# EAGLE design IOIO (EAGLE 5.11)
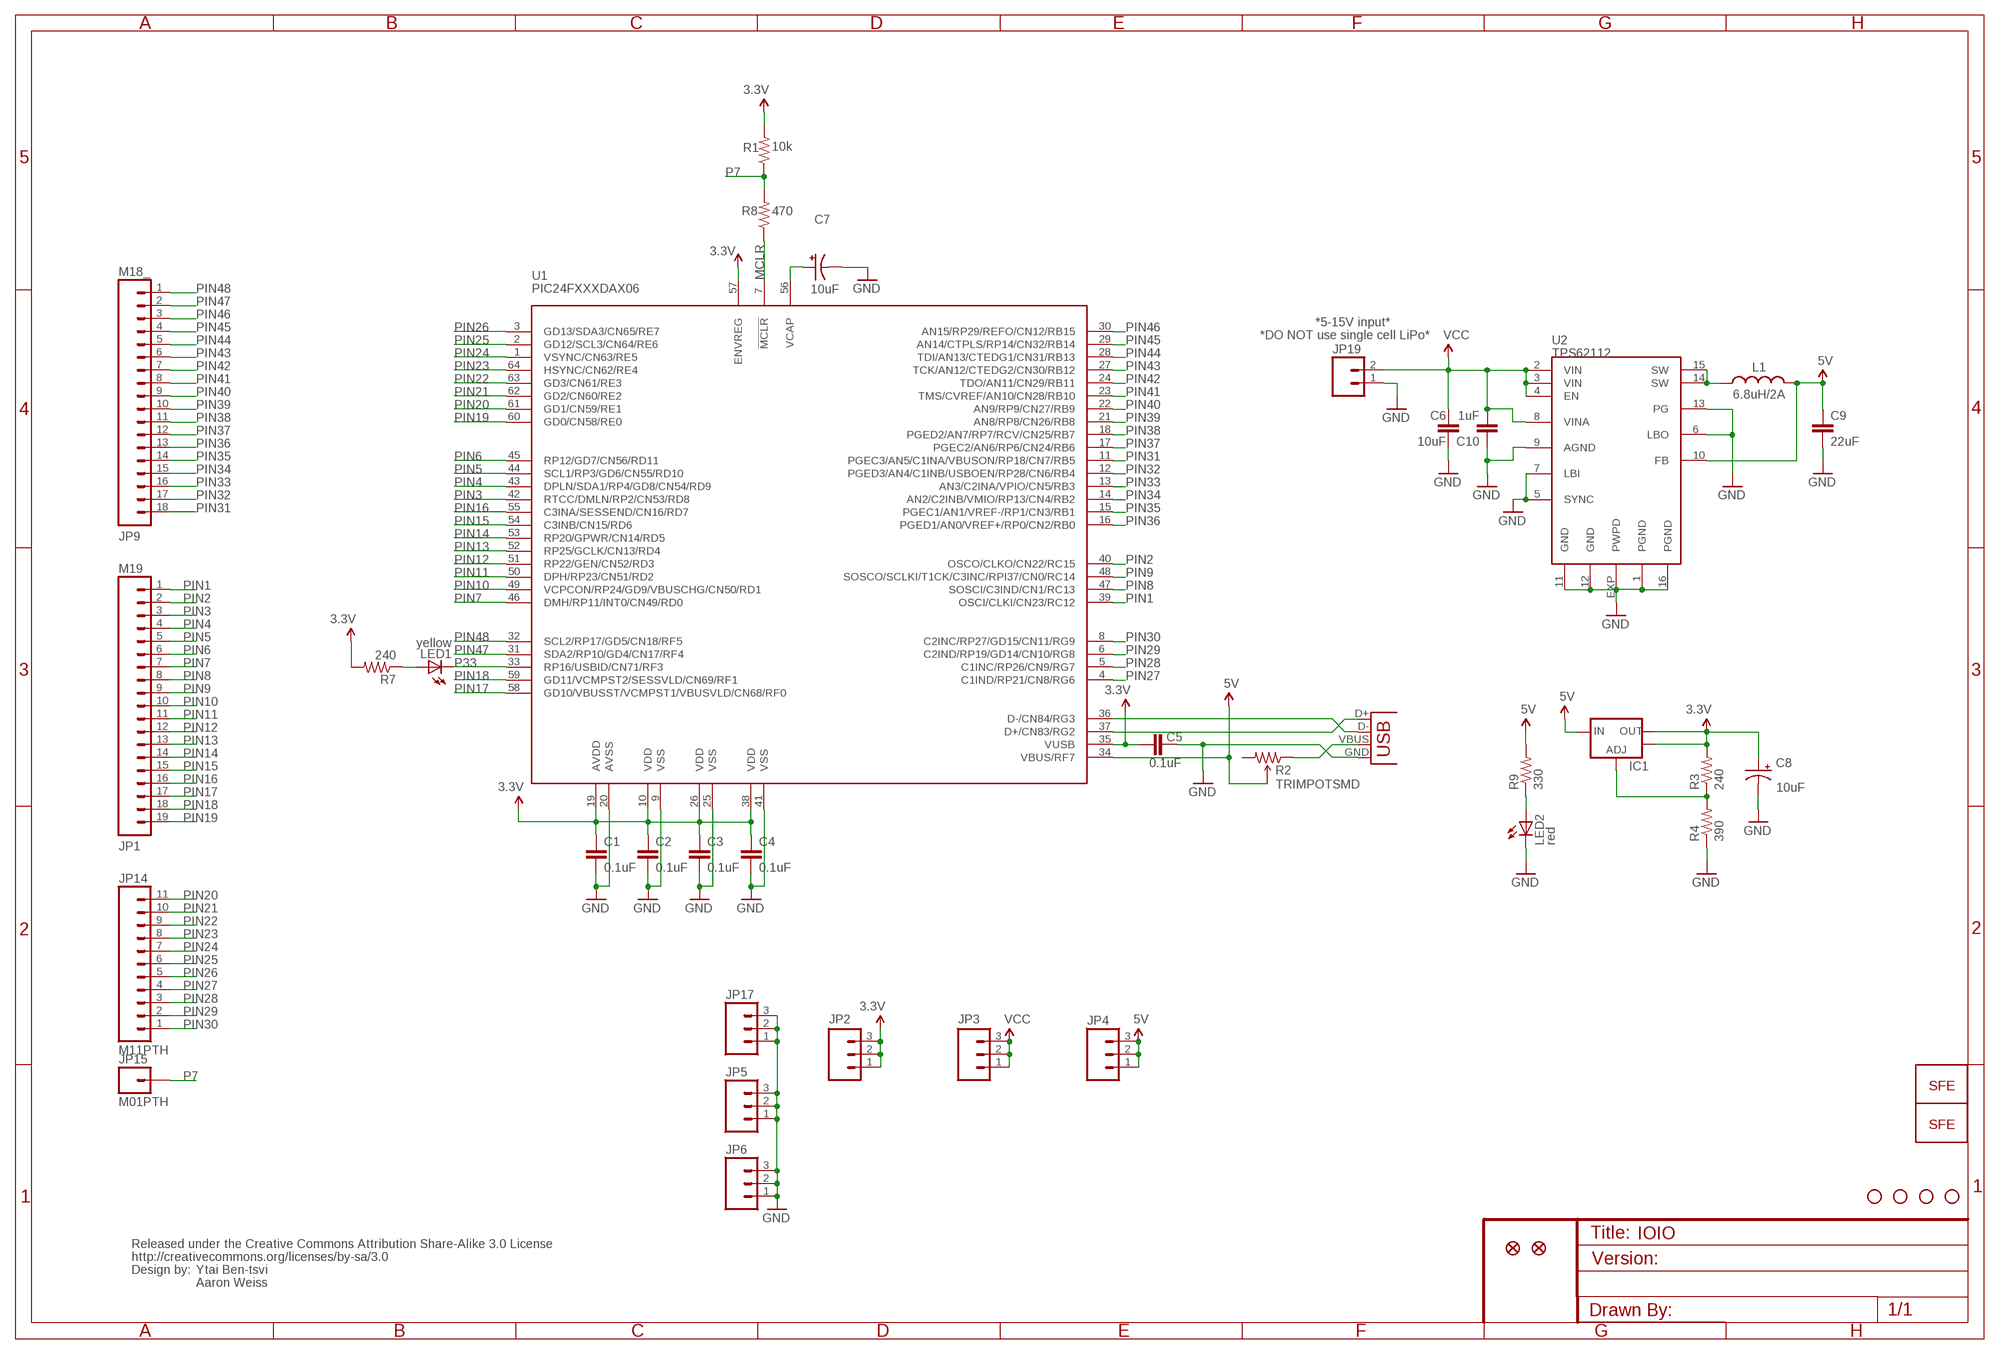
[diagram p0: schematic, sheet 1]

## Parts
C1  0.1uF  CAP0402-CAP  [0402-CAP]
C2  0.1uF  CAP0402-CAP  [0402-CAP]
C3  0.1uF  CAP0402-CAP  [0402-CAP]
C4  0.1uF  CAP0402-CAP  [0402-CAP]
C5  0.1uF  CAP0402-CAP  [0402-CAP]
C6  10uF  CAP1210  [1210]
C7  10uF  CAP_POL1206  [EIA3216]
C8  10uF  CAP_POL1206  [EIA3216]
C9  22uF  CAP1210  [1210]
C10  1uF  CAP0805  [0805]
IC1  V_REG_LM1117SOT223  [SOT223]
JP1  M19  [1X19]
JP2  M03PTH  [1X03]
JP3  M03PTH  [1X03]
JP4  M03PTH  [1X03]
JP5  M03PTH  [1X03]
JP6  M03PTH  [1X03]
JP7  FIDUCIAL1X2  [FIDUCIAL-1X2]
JP8  LOGO-SFENEW  [SFE-NEW-WEBLOGO]
JP9  M18_  [1X18]
JP10  STAND-OFF  [STAND-OFF]
JP11  STAND-OFF  [STAND-OFF]
JP12  STAND-OFF  [STAND-OFF]
JP13  STAND-OFF  [STAND-OFF]
JP14  M11PTH  [1X11]
JP15  M01PTH  [1X01]
JP16  LOGO-SFESK  [SFE-LOGO-FLAME]
JP17  M03PTH  [1X03]
JP18  FIDUCIAL1X2  [FIDUCIAL-1X2]
JP19  M02-JST-2MM-SMT  [JST-2-SMD]
L1  6.8uH/2A  INDUCTORSRU5028  [SRU5028]
LED1  yellow  LED0603  [LED-0603]
LED2  red  LED0603  [LED-0603]
R1  10k  RESISTOR0402-RES  [0402-RES]
R2  TRIMPOTSMD  [TRIMPOT-3MM]
R3  240  RESISTOR0402-RES  [0402-RES]
R4  390  RESISTOR0402-RES  [0402-RES]
R7  240  RESISTOR0402-RES  [0402-RES]
R8  470  RESISTOR0402-RES  [0402-RES]
R9  330  RESISTOR0402-RES  [0402-RES]
U1  PIC24FXXXDAX06  [PIC24FXXX_TQFP64]
U2  TPS62112  TPS6211  [QFN16-4X4]
U$1  CREATIVE_COMMONS  [CREATIVE_COMMONS]
X1  USB-A-SMD  [USB-A-S-NOSILK-FEMALE]

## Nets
3.3V: C1.1 C2.1 C3.1 C4.1 C5.1 C8.A(+) IC1.2(OUT) IC1.4(OUT) JP2.1 JP2.2 JP2.3 R1.2 R3.2 R7.2 U1.10(VDD) U1.19(AVDD) U1.26(VDD) U1.35(VUSB) U1.38(VDD) U1.57(ENVREG)
5V: C9.1 IC1.3(IN) JP4.1 JP4.2 JP4.3 L1.2 R2.2(WIPER) R9.2 U1.34(VBUS/RF7) U2.10(FB)
GND: C1.2 C2.2 C3.2 C4.2 C5.2 C6.2 C7.C(-) C8.C(-) C9.2 C10.1 JP5.1 JP5.2 JP5.3 JP6.1 JP6.2 JP6.3 JP17.1 JP17.2 JP17.3 JP19.1 LED2.C R4.1 U1.9(VSS) U1.20(AVSS) U1.25(VSS) U1.41(VSS) U2.1(PGND) U2.5(SYNC) U2.6(LBO) U2.7(LBI) U2.9(AGND) U2.11(GND) U2.12(GND) U2.13(PG) U2.16(PGND) U2.EXP(PWPD) X1.GND
MCLR: R8.1 U1.7(!MCLR)
N$1: IC1.1(ADJ) R3.1 R4.2
N$2: LED1.A R7.1
N$3: LED2.A R9.1
N$5: C7.A(+) U1.56(VCAP)
N$6: U1.36(D-/CN84/RG3) X1.D-
N$7: U1.37(D+/CN83/RG2) X1.D+
N$8: R2.1(CCW) X1.VBUS
P7: JP15.1 R1.1 R8.2
P33: LED1.C U1.33(RP16/USBID/CN71/RF3)
PIN1: JP1.1 U1.39(OSCI/CLKI/CN23/RC12)
PIN2: JP1.2 U1.40(OSCO/CLKO/CN22/RC15)
PIN3: JP1.3 U1.42(RTCC/DMLN/RP2/CN53/RD8)
PIN4: JP1.4 U1.43(DPLN/SDA1/RP4/GD8/CN54/RD9)
PIN5: JP1.5 U1.44(SCL1/RP3/GD6/CN55/RD10)
PIN6: JP1.6 U1.45(RP12/GD7/CN56/RD11)
PIN7: JP1.7 U1.46(DMH/RP11/INT0/CN49/RD0)
PIN8: JP1.8 U1.47(SOSCI/C3IND/CN1/RC13)
PIN9: JP1.9 U1.48(SOSCO/SCLKI/T1CK/C3INC/RPI37/CN0/RC14)
PIN10: JP1.10 U1.49(VCPCON/RP24/GD9/VBUSCHG/CN50/RD1)
PIN11: JP1.11 U1.50(DPH/RP23/CN51/RD2)
PIN12: JP1.12 U1.51(RP22/GEN/CN52/RD3)
PIN13: JP1.13 U1.52(RP25/GCLK/CN13/RD4)
PIN14: JP1.14 U1.53(RP20/GPWR/CN14/RD5)
PIN15: JP1.15 U1.54(C3INB/CN15/RD6)
PIN16: JP1.16 U1.55(C3INA/SESSEND/CN16/RD7)
PIN17: JP1.17 U1.58(GD10/VBUSST/VCMPST1/VBUSVLD/CN68/RF0)
PIN18: JP1.18 U1.59(GD11/VCMPST2/SESSVLD/CN69/RF1)
PIN19: JP1.19 U1.60(GD0/CN58/RE0)
PIN20: JP14.11 U1.61(GD1/CN59/RE1)
PIN21: JP14.10 U1.62(GD2/CN60/RE2)
PIN22: JP14.9 U1.63(GD3/CN61/RE3)
PIN23: JP14.8 U1.64(HSYNC/CN62/RE4)
PIN24: JP14.7 U1.1(VSYNC/CN63/RE5)
PIN25: JP14.6 U1.2(GD12/SCL3/CN64/RE6)
PIN26: JP14.5 U1.3(GD13/SDA3/CN65/RE7)
PIN27: JP14.4 U1.4(C1IND/RP21/CN8/RG6)
PIN28: JP14.3 U1.5(C1INC/RP26/CN9/RG7)
PIN29: JP14.2 U1.6(C2IND/RP19/GD14/CN10/RG8)
PIN30: JP14.1 U1.8(C2INC/RP27/GD15/CN11/RG9)
PIN31: JP9.18 U1.11(PGEC3/AN5/C1INA/VBUSON/RP18/CN7/RB5)
PIN32: JP9.17 U1.12(PGED3/AN4/C1INB/USBOEN/RP28/CN6/RB4)
PIN33: JP9.16 U1.13(AN3/C2INA/VPIO/CN5/RB3)
PIN34: JP9.15 U1.14(AN2/C2INB/VMIO/RP13/CN4/RB2)
PIN35: JP9.14 U1.15(PGEC1/AN1/VREF-/RP1/CN3/RB1)
PIN36: JP9.13 U1.16(PGED1/AN0/VREF+/RP0/CN2/RB0)
PIN37: JP9.12 U1.17(PGEC2/AN6/RP6/CN24/RB6)
PIN38: JP9.11 U1.18(PGED2/AN7/RP7/RCV/CN25/RB7)
PIN39: JP9.10 U1.21(AN8/RP8/CN26/RB8)
PIN40: JP9.9 U1.22(AN9/RP9/CN27/RB9)
PIN41: JP9.8 U1.23(TMS/CVREF/AN10/CN28/RB10)
PIN42: JP9.7 U1.24(TDO/AN11/CN29/RB11)
PIN43: JP9.6 U1.27(TCK/AN12/CTEDG2/CN30/RB12)
PIN44: JP9.5 U1.28(TDI/AN13/CTEDG1/CN31/RB13)
PIN45: JP9.4 U1.29(AN14/CTPLS/RP14/CN32/RB14)
PIN46: JP9.3 U1.30(AN15/RP29/REFO/CN12/RB15)
PIN47: JP9.2 U1.31(SDA2/RP10/GD4/CN17/RF4)
PIN48: JP9.1 U1.32(SCL2/RP17/GD5/CN18/RF5)
SW: L1.1 U2.14(SW) U2.15(SW)
VCC: C6.1 C10.2 JP3.1 JP3.2 JP3.3 JP19.2 U2.2(VIN) U2.3(VIN) U2.4(EN) U2.8(VINA)
Unconnected: R2.3(CW)

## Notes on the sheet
- *5-15V input*
- *DO NOT use single cell LiPo*
- Ytai Ben-tsvi
- Aaron Weiss

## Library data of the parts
C1-C6 C9 C10 = SparkFun:CAP: Capacitor
C7 C8 = SparkFun:CAP_POL: Capacitor Polarized
IC1 = SparkFun:V_REG_LM1117: Voltage Regulator LM1117 Standard adjustable voltage regulator but in SMD form. Spark Fun Electronics SKU : COM-00595
JP1 = SparkFun:M19
JP2-JP6 JP17 = SparkFun:M03: Header 3 Standard 3-pin 0.1" header. Use with straight break away headers (SKU : PRT-00116), right angle break away headers (PRT-00553), swiss pins (PRT-00743), machine pins (PRT-00117), and female headers (PRT-00115). Molex polarized connector foot print use with SKU : PRT-08232 with associated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
JP7 JP18 = SparkFun:FIDUCIAL: Fiducial Alignment Points
JP8 JP16 = SparkFun:LOGO-SFE: Spark Fun Electronics PCB Logo
JP9 = SparkFun:M18
JP10-JP13 = SparkFun:STAND-OFF: Stand Off
JP14 = SparkFun:M11: Header 11 Standard 11-pin 0.1" header. Use with straight break away headers (SKU : PRT-00116), right angle break away headers (PRT-00553), swiss pins (PRT-00743), machine pins (PRT-00117), and female headers (PRT-00115).
JP15 = SparkFun:M01: Header 1
JP19 = SparkFun:M02: Header 2
L1 = SparkFun:INDUCTOR: Inductors
LED1 LED2 = SparkFun:LED: LEDs
R1 R3 R4 R7-R9 = SparkFun:RESISTOR: Resistor
R2 = SparkFun:TRIMPOT
U1 = SparkFun:PIC24FXXXDAX06: PIC24FXXXDAX06 PIC24FXXXDA106 / PIC24FXXXDA206
U2 = SparkFun:TPS6211*: TPS62112: 1.5A Step-Down Converter
U$1 = SparkFun:CREATIVE_COMMONS
X1 = SparkFun:USB: USB Connectors USB-B-PTH is fully proven SKU : PRT-00139 USB-miniB is fully proven SKU : PRT-00587 USB-A-PCB is untested. USB-A-H is throughly reviewed, but untested. Spark Fun Electronics SKU : PRT-00437 USB-B-SMT is throughly reviewed, but untested. Needs silkscreen touching up. USB-A-S has not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

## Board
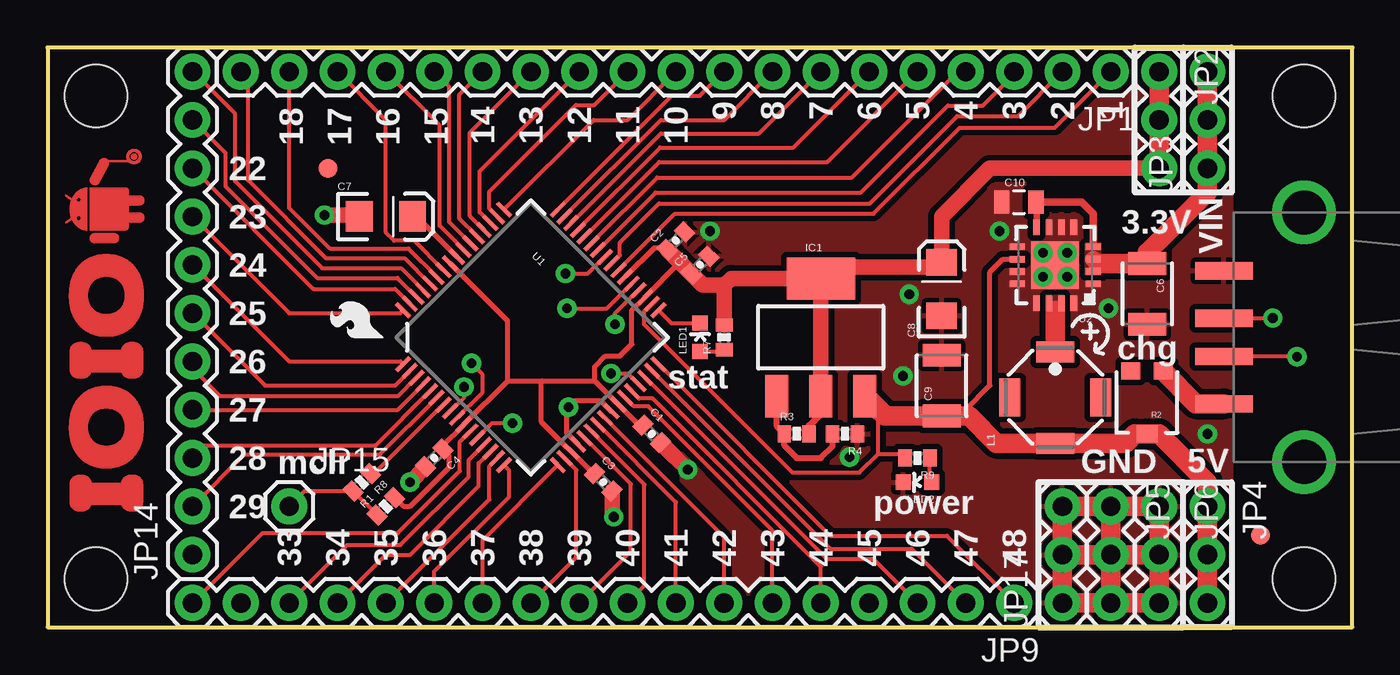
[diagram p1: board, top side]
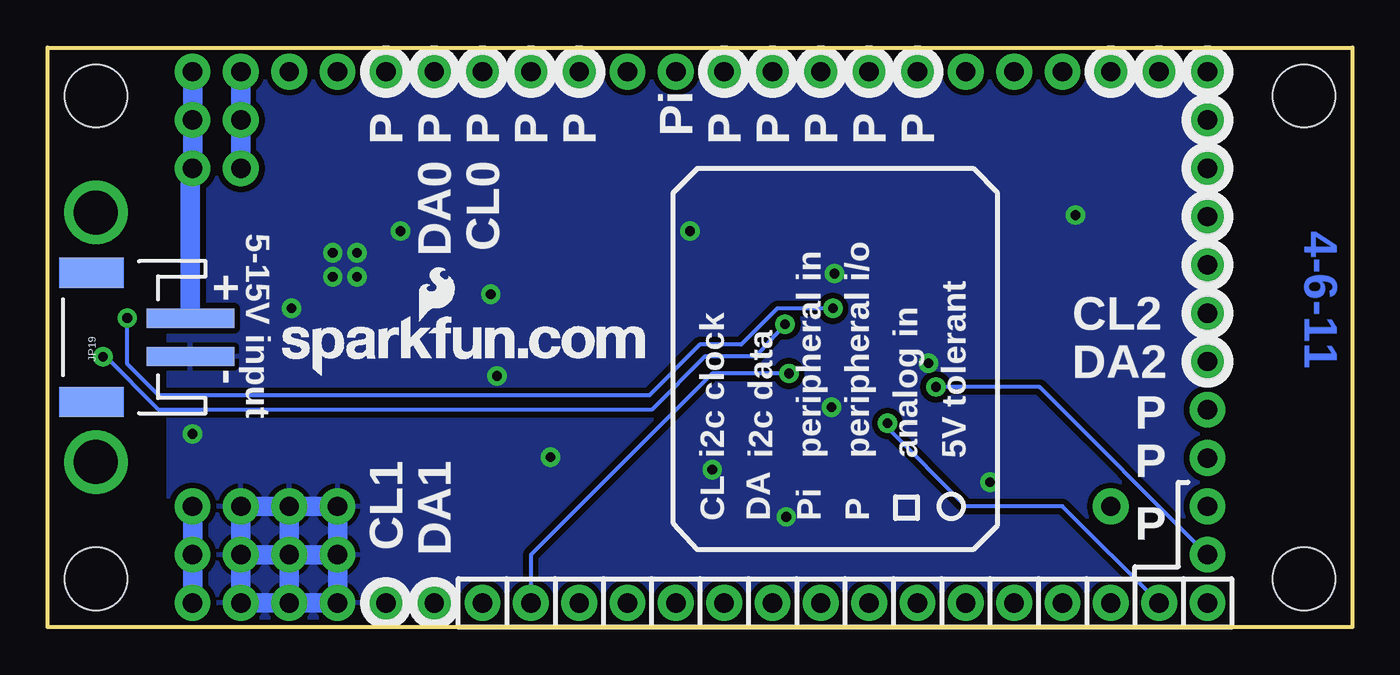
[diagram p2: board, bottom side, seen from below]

Size 68.58 x 30.48 mm. Coordinates in mm from the lower left corner, seen from the top.
Outline: 0,0 68.58,0 68.58,30.48 0,30.48 0,0
Copper layers (1*16): Top 0.035mm / dielectric 1.5mm / Bottom 0.035mm
Design rules "SparkFun": minimum track width 8mil, minimum drill 20mil, track to track 8mil, track to pad 8mil, pad to pad 8mil, via to via 8mil, smd to smd 8mil, copper to edge 8mil, drill to drill 8mil, minimum pad ring 12mil, minimum via ring 10mil, stop-mask expansion 4mil, vias tented up to drill 20mil, thermal gap 10mil

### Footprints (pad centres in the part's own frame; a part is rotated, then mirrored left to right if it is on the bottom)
0402-CAP = smd 0.7 x 0.9: 1 -0.65,0; 2 0.65,0
1210 = smd 1.2 x 2: 1 -1.6,0; 2 1.6,0
EIA3216 = smd 1.4 x 1.6: A 1.4,0; C -1.4,0
0805 = smd 0.8 x 1.2: 1 -0.9,0; 2 0.9,0
SOT223 = smd 1.219 x 2.235: 1 -2.311,-3.099; 2 0,-3.099; 3 2.311,-3.099 | smd 3.6 x 2.2: 4 0,3.099
1X19 = drill 1.016 pad 1.88 round: 1 0,0; 2 2.54,0; 3 5.08,0; 4 7.62,0; 5 10.16,0; 6 12.7,0; 7 15.24,0; 8 17.78,0; 9 20.32,0; 10 22.86,0; 11 25.4,0; 12 27.94,0; 13 30.48,0; 14 33.02,0; 15 35.56,0; 16 38.1,0; 17 40.64,0; 18 43.18,0; 19 45.72,0
1X03 = drill 1.016 pad 1.88 round: 1 0,0; 2 2.54,0; 3 5.08,0
FIDUCIAL-1X2 = smd 1 x 1: 1 0,0
1X18 = drill 1.016 pad 1.88 round: 1 0,0; 2 2.54,0; 3 5.08,0; 4 7.62,0; 5 10.16,0; 6 12.7,0; 7 15.24,0; 8 17.78,0; 9 20.32,0; 10 22.86,0; 11 25.4,0; 12 27.94,0; 13 30.48,0; 14 33.02,0; 15 35.56,0; 16 38.1,0; 17 40.64,0; 18 43.18,0
STAND-OFF = hole 3.302: 0,0
1X11 = drill 1.016 pad 1.88 round: 1 0,0; 2 2.54,0; 3 5.08,0; 4 7.62,0; 5 10.16,0; 6 12.7,0; 7 15.24,0; 8 17.78,0; 9 20.32,0; 10 22.86,0; 11 25.4,0
1X01 = drill 1.016 pad 1.88 round: 1 0,0
JST-2-SMD = smd 1 x 4.6: 1 -1,-3.7; 2 1,-3.7 | smd 1.6 x 3.4: NC1 -3.4,1.5; NC2 3.4,1.5
SRU5028 = smd 1.1 x 2: 1 2.4,0; 2 -2.4,0 | smd 2 x 1.1: P$1 0,2.4; P$2 0,-2.4
LED-0603 = smd 0.8 x 0.8: A 0,-0.75; C 0,0.75
0402-RES = smd 0.7 x 0.9: 1 -0.65,0; 2 0.65,0
TRIMPOT-3MM = smd 1 x 0.9: 1 -0.85,-1.65; 3 0.85,-1.65 | smd 1.1 x 0.9: 2 0,1.65
PIC24FXXX_TQFP64 = smd 0.22 x 1: 1 -3.75,-5.75; 2 -3.25,-5.75; 3 -2.75,-5.75; 4 -2.25,-5.75; 5 -1.75,-5.75; 6 -1.25,-5.75; 7 -0.75,-5.75; 8 -0.25,-5.75; 9 0.25,-5.75; 10 0.75,-5.75; 11 1.25,-5.75; 12 1.75,-5.75; 13 2.25,-5.75; 14 2.75,-5.75; 15 3.25,-5.75; 16 3.75,-5.75; 33 3.75,5.75; 34 3.25,5.75; 35 2.75,5.75; 36 2.25,5.75; 37 1.75,5.75; 38 1.25,5.75; 39 0.75,5.75; 40 0.25,5.75; 41 -0.25,5.75; 42 -0.75,5.75; 43 -1.25,5.75; 44 -1.75,5.75; 45 -2.25,5.75; 46 -2.75,5.75; 47 -3.25,5.75; 48 -3.75,5.75 | smd 1 x 0.22: 17 5.75,-3.75; 18 5.75,-3.25; 19 5.75,-2.75; 20 5.75,-2.25; 21 5.75,-1.75; 22 5.75,-1.25; 23 5.75,-0.75; 24 5.75,-0.25; 25 5.75,0.25; 26 5.75,0.75; 27 5.75,1.25; 28 5.75,1.75; 29 5.75,2.25; 30 5.75,2.75; 31 5.75,3.25; 32 5.75,3.75; 49 -5.75,3.75; 50 -5.75,3.25; 51 -5.75,2.75; 52 -5.75,2.25; 53 -5.75,1.75; 54 -5.75,1.25; 55 -5.75,0.75; 56 -5.75,0.25; 57 -5.75,-0.25; 58 -5.75,-0.75; 59 -5.75,-1.25; 60 -5.75,-1.75; 61 -5.75,-2.25; 62 -5.75,-2.75; 63 -5.75,-3.25; 64 -5.75,-3.75
QFN16-4X4 = smd 0.8 x 0.35: 1 -2,0.975; 2 -2,0.325; 3 -2,-0.325; 4 -2,-0.975; 9 2,-0.975; 10 2,-0.325; 11 2,0.325; 12 2,0.975 | smd 0.35 x 0.8: 5 -0.975,-2; 6 -0.325,-2; 7 0.325,-2; 8 0.975,-2; 13 0.975,2; 14 0.325,2; 15 -0.325,2; 16 -0.975,2 | smd 2.5 x 2.5: EXP 0,0
USB-A-S-NOSILK-FEMALE = smd 3 x 0.9: D+ 4.212,-1; D- 4.212,1; GND 4.212,-3.5; VBUS 4.212,3.5 | drill 2.311 round: P$5 0,-6.566; P$6 0,6.566

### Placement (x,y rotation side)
C1  31.75,10.16 315 top
C2  33.02,20.32 45 top
C3  29.21,7.62 315 top
C4  20.32,8.89 225 top
C5  34.29,19.05 45 top
C6  57.78,17.53 270 top
C7  17.78,21.59 0 top
C8  46.99,17.78 90 top
C9  46.99,12.7 90 top
C10  51.05,22.35 0 top
IC1  40.64,15.24 0 top
JP1  55.88,29.21 180 top
JP2  58.42,29.21 270 top
JP3  60.96,24.13 90 top
JP4  60.96,6.35 270 top
JP5  55.88,6.35 270 top
JP6  58.42,6.35 270 top
JP7  63.75,4.83 0 top
JP8  56.26,13.21 0 bottom
JP9  50.8,1.27 180 top
JP10  66.04,27.94 0 top
JP11  66.04,2.54 0 top
JP12  2.54,27.94 0 top
JP13  2.54,2.54 0 top
JP14  7.62,3.81 90 top
JP15  12.7,6.35 0 top
JP16  17.65,15.24 90 top
JP17  53.34,1.27 90 top
JP18  14.73,24.13 0 top
JP19  64.77,15.24 90 bottom
L1  52.96,12.06 90 top
LED1  34.29,15.24 0 top
LED2  45.72,7.62 90 top
R1  17.78,6.35 45 top
R2  57.78,11.81 180 top
R3  39.37,10.16 0 top
R4  41.91,10.16 180 top
R7  35.56,15.24 90 top
R8  16.51,7.62 225 top
R9  45.72,8.89 180 top
U1  25.4,15.24 315 top
U2  52.96,19.02 180 top
U$1  not placed on the board
U$6  SPARKFUN_ANDROID-IOIO  [SPARKFUN_ANDROID-IOIO-LARGE]  5.08,6.1 90 top
X1  66.04,15.24 180 top

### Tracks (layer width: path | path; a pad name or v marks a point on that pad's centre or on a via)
3.3V
  Top 0.254: U1.38 31.88,19.94 32.48,19.94 C2.1 | U1.35 | U1.35 33.23,19.19 | 28.75,12.95 30,11.71 U1.26 31.08,10.62 C1.1 | U1.35 30.71,16.66 30.71,14.88 30.07,14.25 29.31,14.25 28.75,13.69 28.75,12.95 | 24.18,12.95 25.98,12.95 | 25.98,12.95 28.75,12.95 | 24.18,12.95 U1.10 20.78,9.55 C4.1 21.11,9.02 21.11,8.41 19.05,6.35 18.7,6.35 R1.2 | 25.98,12.95 25.93,12.9 25.93,10.82 28.67,8.08 C3.1 28.67,8.08 U1.19 | 24.18,12.95 24.18,16.11 U1.57
  Top 0.381: IC1.2 40.64,11.2 40.02,10.58 R3.2
  Top 0.813: 35.56,17.98 R7.2 | 35.56,17.98 35.92,18.34 IC1.4 | C2.1 33.23,19.19 C5.1 34.44,17.98 35.56,17.98 | IC1.4 41.22,18.92 46.99,18.92 C8.A 46.99,21.59 49.53,24.13 JP2.3 | IC1.4 IC1.2
  Top 1.016: JP2.1 JP2.2 JP2.3
  Bottom 1.016: JP2.3 JP2.1
5V
  Top 0.203: 43.66,9.12 42.67,8.13 39.14,8.13 31.34,15.93 31.34,16.59 U1.34 | 43.66,9.12 43.66,11.43 | 43.66,9.12 44.84,9.12 R9.2
  Top 0.254: U2.10 50.21,19.35 49.53,18.67 49.53,12.7 48.26,11.43 48.26,11.1
  Top 1.016: JP4.3 JP4.2 JP4.1 60.96,7.62 58.42,10.16 R2.2 57.15,10.16 56.66,9.66 L1.2 49.87,9.66 48.44,11.1 48.26,11.1 C9.1 44.07,11.1 | 44.07,11.1 43.99,11.1 43.66,11.43 | IC1.3 43.03,12.14 44.07,11.1
  Bottom 1.016: JP4.1 JP4.3
GND  (via drill 0.51, 0.51 pad 0.25)
  Top 0.203: U1.9 22.86,12.34 22.86,13.28 v22.28,13.87 | v27.23,18.59 28.4,18.59 U1.41
  Top 0.254: U1.20 27.91,9.58 27.28,10.21 27.28,11.46 v27.38,11.56 27.74,11.91 29.06,11.91 29.62,11.35 U1.25
  Top 0.813: C1.2 32.99,8.91 v33.64,8.28 | C4.2 v19.05,7.62 | C7.C 16.3,21.67 v14.55,21.67 | C3.2 29.67,6 v29.76,5.79
  Top 1.016: JP5.3 JP5.1 | JP5.3 JP6.3 JP6.2 | JP6.2 JP6.1 JP5.1 | JP5.1 JP17.3 JP17.2 | JP17.2 JP6.2 | JP17.2 JP17.1 JP5.3
  Bottom 1.016: JP5.3 JP5.1 | JP5.3 JP6.3 JP6.2 | JP6.2 JP6.1 JP5.1 | JP5.1 JP17.3 JP17.2 | JP17.2 JP6.2 | JP17.2 JP17.1 JP5.3
  other vias: 42.14,8.94 44.96,13.21 45.29,17.5 34.82,20.83 52.32,19.68 52.32,18.41 53.59,18.41 53.59,19.68 55.75,16.76 50.04,20.83 60.96,10.16
  pour Bottom (isolate 0.305): 6.35,30.48 62.23,30.48 62.23,0 6.35,0
  pour Top (isolate 0.305): 33.3,30.35 33.3,-0.13 62.23,0 62.23,30.48
  pour Top (isolate 0.305, no thermals): 49.53,21.59 49.53,16.51 55.5,16.51 55.5,21.59
  pour Top (no thermals): 49.53,21.59 49.53,23.24 50.67,23.24 50.67,21.59
MCLR
  Top 0.203: U1.7 17.18,8.08 R8.1
N$1
  Top 0.305: IC1.1 38.33,10.55 R3.1 38.72,9.54 39.37,8.89 40.64,8.89 41.26,9.51 R4.2
N$2
  Top 0.203: LED1.A 35.46,14.49 R7.1
N$3
  Top 0.203: R9.1 46.37,7.72 LED2.A
N$5
  Top 0.254: U1.56 19.41,21.59 C7.A
N$6  (via drill 0.51)
  Top 0.203: v29.82,15.93 29.82,16.48 U1.36 | X1.D- 65.64,14.24 v65.66,14.22
  Bottom 0.203: v29.82,15.93 31.37,14.22 34.04,14.22 36.83,11.43 62.74,11.43 65.53,14.22 v65.66,14.22
N$7  (via drill 0.51)
  Top 0.203: 29.91,17.27 U1.37 29.4,16.76 v27.3,16.76 | X1.D+ 64.37,16.24 v64.39,16.26
  Bottom 0.203: v27.3,16.76 30.23,16.76 32.13,14.86 34.29,14.86 36.96,12.19 62.74,12.19 64.39,13.84 v64.39,16.26
N$8
  Top 1.016: X1.VBUS 60.36,11.74 R2.1
P7
  Top 0.203: R1.1 R8.2 13.51,7.16 JP15.1
P33
  Top 0.203: LED1.C 32.78,15.99 U1.33
PIN1
  Top 0.203: U1.39 32.96,21.74 43.41,21.74 47.93,26.26 52.93,26.26 JP1.1
PIN2
  Top 0.203: U1.40 30.07,19.56 30.07,20.22 32.13,22.28 43.2,22.28 47.8,26.87 51,26.87 JP1.2
PIN3
  Top 0.203: U1.42 31.96,22.86 42.75,22.86 47.32,27.43 49.15,27.43 50.8,29.08 JP1.3
PIN4
  Top 0.203: U1.43 32.04,23.65 42.27,23.65 47.83,29.21 JP1.4
PIN5
  Top 0.203: U1.44 32.15,24.46 40.97,24.46 JP1.5
PIN6
  Top 0.203: U1.45 32.2,25.22 39.19,25.22 JP1.6
PIN7
  Top 0.203: U1.46 32.23,25.96 37.39,25.96 JP1.7
PIN8
  Top 0.203: U1.47 32.23,26.67 35.56,26.67 JP1.8
PIN9
  Top 0.203: U1.48 32.8,27.94 34.29,27.94 JP1.9
PIN10
  Top 0.203: U1.49 28.7,26.67 30.48,26.67 JP1.10
PIN11
  Top 0.203: U1.50 23.22,22.02 23.22,22.91 27.76,27.46 28.73,27.46 JP1.11
PIN12
  Top 0.203: U1.51 22.71,21.82 22.71,23.98 JP1.12
PIN13
  Top 0.203: U1.52 22.92,20.9 22.2,21.61 22.2,26.01 JP1.13
PIN14
  Top 0.203: U1.53 22.57,20.56 21.64,21.49 21.64,27.99 JP1.14
PIN15
  Top 0.203: U1.54 21.11,21.31 21.11,28.42 JP1.15
PIN16
  Top 0.203: U1.55 20.6,21.11 20.6,26.39 JP1.16
PIN17
  Top 0.203: U1.58 19.26,20.32 18.21,20.32 17.78,20.75 17.78,26.67 JP1.17
PIN18
  Top 0.203: U1.59 18.96,19.91 14.83,19.91 12.7,22.05 JP1.18
PIN19
  Top 0.203: U1.60 18.76,19.41 14.63,19.41 10.54,23.5 10.54,28.83 JP1.19
PIN20
  Top 0.203: U1.61 18.59,18.87 14.43,18.87 9.86,23.44 9.86,27 7.64,29.21 JP14.11
PIN21
  Top 0.203: U1.62 18.39,18.36 14.17,18.36 9.35,23.19 9.35,24.94 JP14.10
PIN22
  Top 0.203: U1.63 18.26,17.78 13.97,17.78 JP14.9
PIN23
  Top 0.203: U1.64 18.54,16.51 12.7,16.51 JP14.8
PIN24
  Top 0.203: U1.1 18.54,13.97 12.7,13.97 JP14.7
PIN25
  Top 0.203: U1.2 18.26,12.7 11.43,12.7 JP14.6
PIN26
  Top 0.203: U1.3 18.44,12.17 9.04,12.17 7.62,13.59 JP14.5
PIN27
  Top 0.203: U1.4 18.41,11.43 JP14.4
PIN28
  Top 0.203: U1.5 17.25,9.56 17.25,9.55 8.28,9.55 JP14.3
PIN29
  Top 0.203: U1.6 17.46,9.07 10.34,9.07 JP14.2
PIN30  (via drill 0.51)
  Top 0.203: U1.8 21.89,12.09 v21.89,12.62
  Bottom 0.203: v21.89,12.62 16.43,12.62 JP14.1
PIN31
  Top 0.203: U1.11 21.67,9.74 21.67,8.2 18.41,4.95 11.3,4.95 JP9.18
PIN32  (via drill 0.51)
  Top 0.203: v24.43,10.72 23.35,10.72 U1.12
  Bottom 0.203: JP9.17 15.24,6.35 20.32,6.35 24.43,10.46 v24.43,10.72
PIN33
  Top 0.203: U1.13 22.12,8.78 22.12,7.9 18.54,4.32 15.75,4.32 JP9.16
PIN34
  Top 0.203: U1.14 22.66,8.61 22.66,7.42 19.05,3.81 17.78,3.81 JP9.15
PIN35
  Top 0.203: U1.15 23.22,8.46 23.22,6.71 JP9.14
PIN36
  Top 0.203: JP9.13 20.32,2.92 24.26,6.86 24.26,8.25 U1.16
PIN37
  Top 0.203: JP9.12 22.86,4.57 U1.17
PIN38
  Top 0.203: U1.18 27.79,8.26 27.79,3.66 JP9.11
PIN39
  Top 0.203: U1.21 30.66,7.52 30.66,3.99 JP9.10
PIN40
  Top 0.203: U1.22 28.6,10.29 28.6,10.27 31.37,7.49 31.37,2.16 JP9.9
PIN41
  Top 0.203: U1.23 33.02,6.56 JP9.8
PIN42
  Top 0.203: U1.24 35.56,4.73 JP9.7
PIN43
  Top 0.203: U1.27 30.81,11.61 31.57,11.61 38.1,5.08 JP9.6
PIN44
  Top 0.203: U1.28 30.72,12.41 30.72,12.39 31.09,12.01 31.8,12.01 40.64,3.17 JP9.5
PIN45  (via drill 0.51)
  Top 0.203: 31.07,12.77 U1.29 30.49,13.34 v29.62,13.34
  Bottom 0.203: v29.62,13.34 33.66,13.34 43.18,3.81 JP9.4
PIN46
  Top 0.203: U1.30 40.95,3.58 43.41,3.58 JP9.3
PIN47
  Top 0.203: U1.31 32.56,12.68 41.15,4.12 45.41,4.12 JP9.2
PIN48
  Top 0.203: U1.32 41.14,4.8 47.27,4.8 JP9.1
SW
  Top 0.254: 52.96,16.64 52.96,16.7 U2.15
  Top 1.016: L1.1 52.96,16.64
  pour Top (isolate 0.305, no thermals): 53.47,16.64 53.47,17.53 52.45,17.53 52.45,16.64
VCC
  Top 0.33: U2.8 51.98,22.28 C10.2 52.07,22.36
  Top 0.406: U2.4 54.96,21.75 54.36,22.35 C10.2
  Top 0.889: U2.3 55.18,19.13
  Top 1.016: JP3.3 JP3.1 60.96,22.86 57.78,19.68 C6.1 55.18,19.13
  Bottom 1.016: JP3.3 JP3.2 JP3.1 61.07,24.02 JP19.2
  pour Top (isolate 0.305, no thermals): 54.48,20.19 54.48,18.54 55.37,18.54 55.37,20.19

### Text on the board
Bottom: 4-6-11
tPlace: 9 | 8 | 7 | 6 | 5 | 4 | 3 | 2 | 1 | 18 | 17 | 16 | 15 | 14 | 13 | 12 | 11 | 10 | 22 | 3.3V | 23 | VIN | 24 | 25 | chg | 26 | stat | 27 | 28 | mclr | GND | 5V | 29 | power | 33 | 34 | 35 | 36 | 37 | 38 | 39 | 40 | 41 | 42 | 43 | 44 | 45 | 46 | 47 | 48
bPlace: Pi | P | P | P | P | P | P | P | P | P | P | CL0 | DA0 | 5-15V input | + | CL2 | - | DA2 | P | 5V tolerant | analog in | peripheral i/o | peripheral in | i2c data | i2c clock | DA1 | CL1 | P | P | Pi | DA | CL | P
